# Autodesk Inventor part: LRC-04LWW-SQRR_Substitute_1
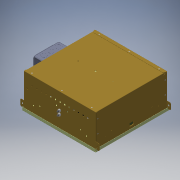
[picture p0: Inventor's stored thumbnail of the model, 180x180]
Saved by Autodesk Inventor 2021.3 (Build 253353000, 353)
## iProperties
Part Number: LRC-04LWW-SQRR_Substitute_1
Material: Generic
Document SubType Name: Modeling
Designer: JChurch
Manufacturer: Standard
Standards Organization: Custom
Density: 1 g/cm^3
Appearance: Smooth - Black
Author: JChurch
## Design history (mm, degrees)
derived "LRC-04LWW-SQRR.iam"
body "Solid9"
node "830557-00-00.iam:1::830557-PAN.ipt:1"
node "830557-00-00.iam:1::830557-FLANGE.ipt:2"
body "Solid10"
node "830557-00-00.iam:1::506010-00-38 SQUEEZED.ipt:1"
body "Solid11"
node "830557-00-00.iam:1::506010-00-38 SQUEEZED.ipt:2"
body "Solid12"
node "830557-00-00.iam:1::506010-00-38 SQUEEZED.ipt:3"
body "Solid13"
node "830557-00-00.iam:1::506010-00-38 SQUEEZED.ipt:4"
body "Solid14"
node "830557-00-00.iam:1::506010-00-38 SQUEEZED.ipt:5"
body "Solid15"
node "830557-00-00.iam:1::506010-00-38 SQUEEZED.ipt:6"
body "Solid16"
node "830557-00-00.iam:1::506010-00-38 SQUEEZED.ipt:7"
body "Solid17"
node "830557-00-00.iam:1::506010-00-38 SQUEEZED.ipt:8"
body "Solid18"
node "830557-00-00.iam:1::830557-FLANGE.ipt:3"
body "Solid19"
node "881088-00-00.iam:1::830140-00-00.ipt:1"
body "Solid20"
node "881088-00-00.iam:1::850014-00-00.iam:1::805044-00-00.ipt:1"
body "Solid21"
node "881088-00-00.iam:1::850014-00-00.iam:1::805174-00-00.ipt:1"
body "Solid22"
node "881088-00-00.iam:1::850014-00-00.iam:1::502055-00-00.ipt:1"
body "Solid23"
node "881088-00-00.iam:1::850014-00-00.iam:1::502055-00-00.ipt:2"
body "Solid24"
node "881088-00-00.iam:1::850014-00-00.iam:1::507032-00-00.ipt:1"
body "Solid25"
node "881088-00-00.iam:1::507000-00-00.ipt:1"
body "Solid26"
node "881088-00-00.iam:1::507000-00-00.ipt:2"
body "Solid27"
node "881088-00-00.iam:1::506002-00-00.ipt:1"
body "Solid28"
node "881088-00-00.iam:1::506002-00-00.ipt:2"
body "Solid29"
node "881088-00-00.iam:1::506002-00-00.ipt:3"
body "Solid30"
node "881088-00-00.iam:1::506002-00-00.ipt:4"
body "Solid31"
node "881088-00-00.iam:1::506002-00-00.ipt:5"
body "Solid32"
node "881088-00-00.iam:1::506002-00-00.ipt:6"
body "Solid33"
node "881088-00-00.iam:1::506002-00-00.ipt:7"
body "Solid34"
node "881088-00-00.iam:1::506002-00-00.ipt:8"
body "Solid35"
node "881088-00-00.iam:1::506002-00-00.ipt:9"
body "Solid36"
node "881088-00-00.iam:1::506002-00-00.ipt:10"
body "Solid37"
node "881088-00-00.iam:1::506002-00-00.ipt:11"
body "Solid38"
node "881088-00-00.iam:1::506002-00-00.ipt:12"
body "Solid39"
node "881088-00-00.iam:1::506002-00-00.ipt:13"
body "Solid40"
node "881088-00-00.iam:1::506002-00-00.ipt:14"
body "Solid41"
node "881088-00-00.iam:1::830392-01-00.iam:1::830392-00-00.ipt:1"
body "Solid42"
node "881088-00-00.iam:1::830392-01-00.iam:1::500027-00-00.ipt:1"
body "Solid43"
node "881088-00-00.iam:1::830392-01-00.iam:1::501030-00-00.ipt:1"
body "Solid44"
node "881088-00-00.iam:1::830392-01-00.iam:1::500027-00-00.ipt:2"
body "Solid45"
node "881088-00-00.iam:1::830392-01-00.iam:1::501030-00-00.ipt:2"
body "Solid46"
node "881088-00-00.iam:1::830392-01-00.iam:1::501030-00-00.ipt:3"
body "Solid47"
node "881088-00-00.iam:1::830392-01-00.iam:1::501030-00-00.ipt:4"
body "Solid48"
node "881088-00-00.iam:1::830392-01-00.iam:2::830392-00-00.ipt:1"
body "Solid49"
node "881088-00-00.iam:1::830392-01-00.iam:2::500027-00-00.ipt:1"
body "Solid50"
node "881088-00-00.iam:1::830392-01-00.iam:2::501030-00-00.ipt:1"
body "Solid51"
node "881088-00-00.iam:1::830392-01-00.iam:2::500027-00-00.ipt:2"
body "Solid52"
node "881088-00-00.iam:1::830392-01-00.iam:2::501030-00-00.ipt:2"
body "Solid53"
node "881088-00-00.iam:1::830392-01-00.iam:2::501030-00-00.ipt:3"
body "Solid54"
node "881088-00-00.iam:1::830392-01-00.iam:2::501030-00-00.ipt:4"
body "Solid55"
node "750477-00-XX.iam:1::700100-25-XX.iam:1::700100-25-bkt-s1.ipt"
body "Solid56"
node "750477-00-XX.iam:1::700100-25-XX.iam:1::700100-25-bkt-s1_MIR"
body "Solid57"
node "750477-00-XX.iam:1::700100-25-XX.iam:1::700100-25-RF.ipt:1"
body "Solid58"
node "750477-00-XX.iam:1::700100-25-XX.iam:1::700100-25-RF2.ipt:1"
body "Solid59"
node "750477-00-XX.iam:1::700100-25-XX.iam:1::700100-25-RF2_MIR.ip"
body "Solid60"
node "750477-00-XX.iam:1::700100-25-XX.iam:1::700100-25-RF1.ipt:1"
body "Solid61"
node "750477-00-XX.iam:1::507055-00-38.ipt:1"
body "Solid62"
node "750477-00-XX.iam:1::510120-00-00.ipt:1"
body "Solid63"
node "750477-00-XX.iam:1::507055-00-38.ipt:2"
body "Solid64"
node "725278-01-00.ipt:1"
body "Solid65"
other parameters: "d15" = 61.595, "d16" = 9.525, "d17" = 9.525, "d35" = 5.08
